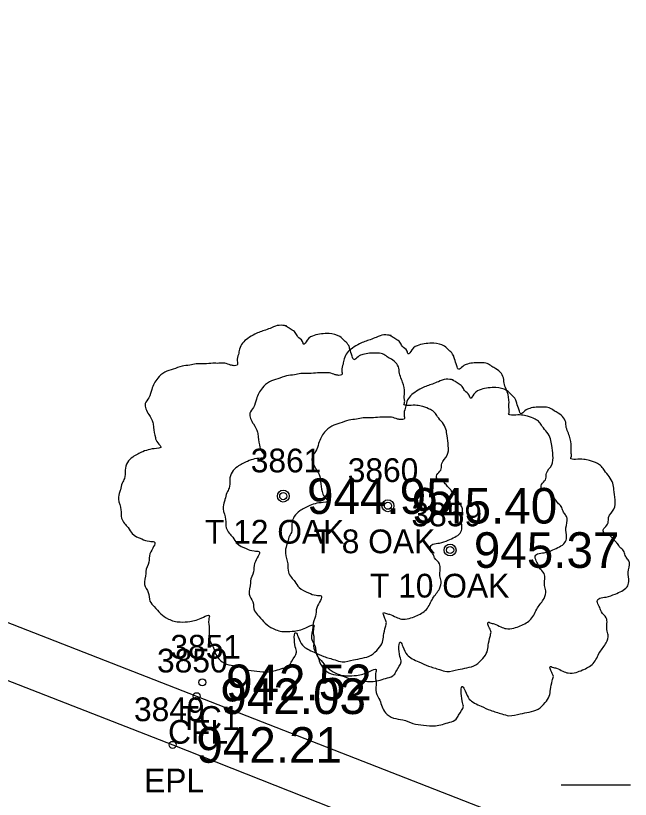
# Model space of a CAD drawing. Extents: x 1575382 to 1578175, y 1099175 to 1101955.
# Drawn here: x 1577597.19 to 1577623.09, y 1100831.49 to 1100864.5 of the extents above; entities that cross this region are included whole.
import ezdxf

# ---------------------------------------------------------------- set-up
doc = ezdxf.new("R2010")
doc.units = 0
for name, color, linetype in [('RD_EX_Conc', 7, 'Continuous'), ('RD_EX_Conc_txCode', 7, 'Continuous'), ('RD_EX_Road', 7, 'Continuous'), ('RD_EX_Road_txCode', 7, 'Continuous'), ('RD_EX_TX_Conc_ELEV', 7, 'Continuous'), ('RD_EX_TX_Road_ELEV', 7, 'Continuous'), ('RD_EX_TX_VEG_ELEV', 7, 'Continuous'), ('RD_EX_UT', 7, 'Continuous'), ('RD_EX_VEG', 7, 'Continuous'), ('RD_EX_VEG_txCode', 7, 'Continuous'), ('RD_HC_Data', 7, 'Continuous'), ('RD_SMD_Locator', 7, 'Continuous')]:
    doc.layers.add(name, color=color, linetype=linetype)

msp = doc.modelspace()

# ---------------------------------------------------------------- linework, layer by layer
at = {"layer": 'RD_EX_Conc'}
msp.add_lwpolyline([(1577521.961, 1100892.215), (1577519.026, 1100884.741), (1577517.864, 1100878.699), (1577519.281, 1100873.69), (1577525.338, 1100868.314), (1577559.486, 1100853.531), (1577604.815, 1100835.833), (1577651.288, 1100817.68)], dxfattribs=at)
at = {"layer": 'RD_EX_Road'}
msp.add_lwpolyline([(1577532.834, 1100925.692), (1577520.073, 1100893.352), (1577517.119, 1100885.443), (1577515.828, 1100878.695), (1577517.186, 1100872.6), (1577524.619, 1100866.376), (1577558.241, 1100851.545), (1577603.805, 1100833.782), (1577650.481, 1100815.34)], dxfattribs=at)
at = {"layer": 'RD_EX_UT'}
msp.add_line((1577620.17, 1100832.105), (1577623.1, 1100832.105), dxfattribs=at)
at = {"layer": 'RD_EX_VEG'}
for centre, radius in [((1577608.465, 1100844.262), 0.25), ((1577608.452, 1100844.243), 0.0001), ((1577612.874, 1100843.856), 0.25), ((1577612.861, 1100843.837), 0.0001), ((1577615.496, 1100841.99), 0.25), ((1577615.483, 1100841.971), 0.0001)]:
    msp.add_circle(centre, radius, dxfattribs=at)
for points in [[(1577608.597, 1100851.43), (1577608.297, 1100851.455), (1577607.972, 1100851.355), (1577607.722, 1100851.255), (1577607.497, 1100851.18), (1577607.272, 1100851.08), (1577606.972, 1100850.905), (1577606.748, 1100850.705), (1577606.623, 1100850.455), (1577606.573, 1100850.23), (1577606.523, 1100849.955), (1577606.523, 1100849.78), (1577606.398, 1100849.755), (1577606.248, 1100849.78), (1577605.998, 1100849.855), (1577605.748, 1100849.855), (1577605.498, 1100849.855), (1577605.148, 1100849.83), (1577604.798, 1100849.83), (1577604.524, 1100849.78), (1577604.199, 1100849.73), (1577603.824, 1100849.605), (1577603.474, 1100849.48), (1577603.174, 1100849.23), (1577602.924, 1100848.756), (1577602.799, 1100848.406), (1577602.649, 1100848.156), (1577602.799, 1100847.706), (1577602.974, 1100847.356), (1577602.999, 1100847.156), (1577603.074, 1100846.732), (1577603.174, 1100846.507), (1577603.299, 1100846.307), (1577603.224, 1100846.282), (1577602.849, 1100846.232), (1577602.549, 1100846.132), (1577602.125, 1100845.907), (1577601.9, 1100845.682), (1577601.8, 1100845.357), (1577601.775, 1100845.007), (1577601.675, 1100844.807), (1577601.6, 1100844.533), (1577601.575, 1100844.458), (1577601.525, 1100844.133), (1577601.625, 1100843.683), (1577601.65, 1100843.333), (1577601.775, 1100843.108), (1577601.925, 1100842.933), (1577602.1, 1100842.683), (1577602.499, 1100842.458), (1577602.824, 1100842.358), (1577603.024, 1100842.334), (1577602.849, 1100841.834), (1577602.799, 1100841.484), (1577602.674, 1100841.084), (1577602.674, 1100841.009), (1577602.624, 1100840.534), (1577602.774, 1100840.209), (1577602.849, 1100839.835), (1577603.024, 1100839.61), (1577603.299, 1100839.31), (1577603.624, 1100839.085), (1577604.124, 1100838.96), (1577604.524, 1100838.985), (1577605.098, 1100839.16), (1577605.348, 1100839.235), (1577605.323, 1100839.06), (1577605.348, 1100838.685), (1577605.348, 1100838.26), (1577605.498, 1100837.935), (1577605.598, 1100837.661), (1577605.748, 1100837.411), (1577606.073, 1100837.186), (1577606.473, 1100837.111), (1577606.897, 1100836.961), (1577607.347, 1100836.886), (1577607.847, 1100836.861), (1577608.447, 1100837.011), (1577608.722, 1100837.136), (1577608.822, 1100837.311), (1577609.022, 1100837.686), (1577608.972, 1100837.91), (1577608.997, 1100838.51), (1577609.096, 1100838.335), (1577609.271, 1100837.985), (1577609.771, 1100837.686), (1577610.171, 1100837.511), (1577610.646, 1100837.361), (1577610.946, 1100837.286), (1577611.42, 1100837.361), (1577611.795, 1100837.436), (1577612.17, 1100837.561), (1577612.47, 1100837.835), (1577612.645, 1100838.11), (1577612.695, 1100838.385), (1577612.77, 1100838.76), (1577612.82, 1100838.935)], [(1577612.82, 1100838.935), (1577612.745, 1100839.11), (1577612.695, 1100839.36), (1577612.77, 1100839.335), (1577612.945, 1100839.285), (1577613.22, 1100839.16), (1577613.445, 1100839.085), (1577613.769, 1100839.11), (1577614.044, 1100839.21), (1577614.494, 1100839.485), (1577614.769, 1100839.96), (1577615.044, 1100840.359), (1577615.119, 1100840.684), (1577615.069, 1100840.909), (1577615.044, 1100841.409), (1577614.844, 1100841.659), (1577614.794, 1100841.784), (1577614.694, 1100842.184), (1577614.769, 1100842.234), (1577615.044, 1100842.284), (1577615.419, 1100842.408), (1577615.694, 1100842.533), (1577615.919, 1100842.708), (1577615.993, 1100842.933), (1577615.969, 1100843.333), (1577616.018, 1100843.733), (1577615.944, 1100843.883), (1577615.844, 1100844.033), (1577615.769, 1100844.233), (1577615.619, 1100844.383), (1577615.519, 1100844.533), (1577615.419, 1100844.632), (1577615.294, 1100844.782), (1577615.119, 1100844.907), (1577614.969, 1100844.957), (1577614.919, 1100845.107), (1577615.069, 1100845.307), (1577615.119, 1100845.407), (1577615.144, 1100845.632), (1577615.369, 1100845.982), (1577615.419, 1100846.382), (1577615.369, 1100846.807), (1577615.319, 1100847.081), (1577615.169, 1100847.356), (1577614.969, 1100847.606), (1577614.844, 1100847.781), (1577614.669, 1100847.906), (1577614.344, 1100848.031), (1577614.094, 1100848.081), (1577613.744, 1100848.081), (1577613.545, 1100848.131), (1577613.57, 1100848.181), (1577613.57, 1100848.331), (1577613.57, 1100848.606), (1577613.495, 1100849.056), (1577613.345, 1100849.555), (1577613.345, 1100849.58), (1577613.245, 1100849.83), (1577613.02, 1100850.03), (1577612.845, 1100850.13), (1577612.645, 1100850.255), (1577612.395, 1100850.28), (1577612.095, 1100850.28), (1577611.82, 1100850.23), (1577611.62, 1100850.13), (1577611.445, 1100850.005), (1577611.37, 1100850.155), (1577611.271, 1100850.455), (1577611.221, 1100850.605), (1577611.071, 1100850.78), (1577610.846, 1100850.98), (1577610.396, 1100851.105), (1577609.771, 1100851.03), (1577609.471, 1100850.83), (1577609.321, 1100850.655), (1577609.271, 1100850.78), (1577609.071, 1100850.98), (1577608.972, 1100851.155), (1577608.797, 1100851.28), (1577608.647, 1100851.38), (1577608.547, 1100851.43)], [(1577613.006, 1100851.023), (1577612.706, 1100851.048), (1577612.381, 1100850.948), (1577612.131, 1100850.849), (1577611.906, 1100850.774), (1577611.681, 1100850.674), (1577611.381, 1100850.499), (1577611.157, 1100850.299), (1577611.032, 1100850.049), (1577610.982, 1100849.824), (1577610.932, 1100849.549), (1577610.932, 1100849.374), (1577610.807, 1100849.349), (1577610.657, 1100849.374), (1577610.407, 1100849.449), (1577610.157, 1100849.449), (1577609.907, 1100849.449), (1577609.557, 1100849.424), (1577609.207, 1100849.424), (1577608.933, 1100849.374), (1577608.608, 1100849.324), (1577608.233, 1100849.199), (1577607.883, 1100849.074), (1577607.583, 1100848.824), (1577607.333, 1100848.35), (1577607.208, 1100848), (1577607.058, 1100847.75), (1577607.208, 1100847.3), (1577607.383, 1100846.95), (1577607.408, 1100846.75), (1577607.483, 1100846.326), (1577607.583, 1100846.101), (1577607.708, 1100845.901), (1577607.633, 1100845.876), (1577607.258, 1100845.826), (1577606.958, 1100845.726), (1577606.534, 1100845.501), (1577606.309, 1100845.276), (1577606.209, 1100844.951), (1577606.184, 1100844.601), (1577606.084, 1100844.401), (1577606.009, 1100844.126), (1577605.984, 1100844.051), (1577605.934, 1100843.727), (1577606.034, 1100843.277), (1577606.059, 1100842.927), (1577606.184, 1100842.702), (1577606.334, 1100842.527), (1577606.509, 1100842.277), (1577606.908, 1100842.052), (1577607.233, 1100841.952), (1577607.433, 1100841.927), (1577607.258, 1100841.428), (1577607.208, 1100841.078), (1577607.083, 1100840.678), (1577607.083, 1100840.603), (1577607.033, 1100840.128), (1577607.183, 1100839.803), (1577607.258, 1100839.429), (1577607.433, 1100839.204), (1577607.708, 1100838.904), (1577608.033, 1100838.679), (1577608.533, 1100838.554), (1577608.933, 1100838.579), (1577609.507, 1100838.754), (1577609.757, 1100838.829), (1577609.732, 1100838.654), (1577609.757, 1100838.279), (1577609.757, 1100837.854), (1577609.907, 1100837.529), (1577610.007, 1100837.254), (1577610.157, 1100837.005), (1577610.482, 1100836.78), (1577610.882, 1100836.705), (1577611.306, 1100836.555), (1577611.756, 1100836.48), (1577612.256, 1100836.455), (1577612.856, 1100836.605), (1577613.131, 1100836.73), (1577613.231, 1100836.905), (1577613.431, 1100837.279), (1577613.381, 1100837.504), (1577613.406, 1100838.104), (1577613.505, 1100837.929), (1577613.68, 1100837.579), (1577614.18, 1100837.279), (1577614.58, 1100837.105), (1577615.055, 1100836.955), (1577615.355, 1100836.88), (1577615.829, 1100836.955), (1577616.204, 1100837.03), (1577616.579, 1100837.155), (1577616.879, 1100837.429), (1577617.054, 1100837.704), (1577617.104, 1100837.979), (1577617.179, 1100838.354), (1577617.229, 1100838.529)], [(1577617.229, 1100838.529), (1577617.154, 1100838.704), (1577617.104, 1100838.954), (1577617.179, 1100838.929), (1577617.354, 1100838.879), (1577617.629, 1100838.754), (1577617.854, 1100838.679), (1577618.178, 1100838.704), (1577618.453, 1100838.804), (1577618.903, 1100839.079), (1577619.178, 1100839.553), (1577619.453, 1100839.953), (1577619.528, 1100840.278), (1577619.478, 1100840.503), (1577619.453, 1100841.003), (1577619.253, 1100841.253), (1577619.203, 1100841.378), (1577619.103, 1100841.777), (1577619.178, 1100841.827), (1577619.453, 1100841.877), (1577619.828, 1100842.002), (1577620.103, 1100842.127), (1577620.328, 1100842.302), (1577620.402, 1100842.527), (1577620.378, 1100842.927), (1577620.427, 1100843.327), (1577620.353, 1100843.477), (1577620.253, 1100843.627), (1577620.178, 1100843.827), (1577620.028, 1100843.976), (1577619.928, 1100844.126), (1577619.828, 1100844.226), (1577619.703, 1100844.376), (1577619.528, 1100844.501), (1577619.378, 1100844.551), (1577619.328, 1100844.701), (1577619.478, 1100844.901), (1577619.528, 1100845.001), (1577619.553, 1100845.226), (1577619.778, 1100845.576), (1577619.828, 1100845.976), (1577619.778, 1100846.4), (1577619.728, 1100846.675), (1577619.578, 1100846.95), (1577619.378, 1100847.2), (1577619.253, 1100847.375), (1577619.078, 1100847.5), (1577618.753, 1100847.625), (1577618.503, 1100847.675), (1577618.153, 1100847.675), (1577617.954, 1100847.725), (1577617.979, 1100847.775), (1577617.979, 1100847.925), (1577617.979, 1100848.2), (1577617.904, 1100848.649), (1577617.754, 1100849.149), (1577617.754, 1100849.174), (1577617.654, 1100849.424), (1577617.429, 1100849.624), (1577617.254, 1100849.724), (1577617.054, 1100849.849), (1577616.804, 1100849.874), (1577616.504, 1100849.874), (1577616.229, 1100849.824), (1577616.029, 1100849.724), (1577615.854, 1100849.599), (1577615.779, 1100849.749), (1577615.68, 1100850.049), (1577615.63, 1100850.199), (1577615.48, 1100850.374), (1577615.255, 1100850.574), (1577614.805, 1100850.699), (1577614.18, 1100850.624), (1577613.88, 1100850.424), (1577613.73, 1100850.249), (1577613.68, 1100850.374), (1577613.48, 1100850.574), (1577613.381, 1100850.749), (1577613.206, 1100850.874), (1577613.056, 1100850.973), (1577612.956, 1100851.023)], [(1577615.628, 1100849.157), (1577615.328, 1100849.182), (1577615.003, 1100849.082), (1577614.753, 1100848.983), (1577614.528, 1100848.908), (1577614.303, 1100848.808), (1577614.004, 1100848.633), (1577613.779, 1100848.433), (1577613.654, 1100848.183), (1577613.604, 1100847.958), (1577613.554, 1100847.683), (1577613.554, 1100847.508), (1577613.429, 1100847.483), (1577613.279, 1100847.508), (1577613.029, 1100847.583), (1577612.779, 1100847.583), (1577612.529, 1100847.583), (1577612.179, 1100847.558), (1577611.829, 1100847.558), (1577611.555, 1100847.508), (1577611.23, 1100847.458), (1577610.855, 1100847.333), (1577610.505, 1100847.208), (1577610.205, 1100846.958), (1577609.955, 1100846.484), (1577609.83, 1100846.134), (1577609.68, 1100845.884), (1577609.83, 1100845.434), (1577610.005, 1100845.084), (1577610.03, 1100844.884), (1577610.105, 1100844.46), (1577610.205, 1100844.235), (1577610.33, 1100844.035), (1577610.255, 1100844.01), (1577609.88, 1100843.96), (1577609.58, 1100843.86), (1577609.156, 1100843.635), (1577608.931, 1100843.41), (1577608.831, 1100843.085), (1577608.806, 1100842.735), (1577608.706, 1100842.535), (1577608.631, 1100842.26), (1577608.606, 1100842.185), (1577608.556, 1100841.861), (1577608.656, 1100841.411), (1577608.681, 1100841.061), (1577608.806, 1100840.836), (1577608.956, 1100840.661), (1577609.131, 1100840.411), (1577609.53, 1100840.186), (1577609.855, 1100840.086), (1577610.055, 1100840.061), (1577609.88, 1100839.562), (1577609.83, 1100839.212), (1577609.705, 1100838.812), (1577609.705, 1100838.737), (1577609.655, 1100838.262), (1577609.805, 1100837.937), (1577609.88, 1100837.563), (1577610.055, 1100837.338), (1577610.33, 1100837.038), (1577610.655, 1100836.813), (1577611.155, 1100836.688), (1577611.555, 1100836.713), (1577612.129, 1100836.888), (1577612.379, 1100836.963), (1577612.354, 1100836.788), (1577612.379, 1100836.413), (1577612.379, 1100835.988), (1577612.529, 1100835.663), (1577612.629, 1100835.388), (1577612.779, 1100835.139), (1577613.104, 1100834.914), (1577613.504, 1100834.839), (1577613.929, 1100834.689), (1577614.378, 1100834.614), (1577614.878, 1100834.589), (1577615.478, 1100834.739), (1577615.753, 1100834.864), (1577615.853, 1100835.039), (1577616.053, 1100835.413), (1577616.003, 1100835.638), (1577616.028, 1100836.238), (1577616.128, 1100836.063), (1577616.303, 1100835.713), (1577616.802, 1100835.413), (1577617.202, 1100835.239), (1577617.677, 1100835.089), (1577617.977, 1100835.014), (1577618.452, 1100835.089), (1577618.826, 1100835.164), (1577619.201, 1100835.289), (1577619.501, 1100835.563), (1577619.676, 1100835.838), (1577619.726, 1100836.113), (1577619.801, 1100836.488), (1577619.851, 1100836.663)], [(1577619.851, 1100836.663), (1577619.776, 1100836.838), (1577619.726, 1100837.088), (1577619.801, 1100837.063), (1577619.976, 1100837.013), (1577620.251, 1100836.888), (1577620.476, 1100836.813), (1577620.801, 1100836.838), (1577621.075, 1100836.938), (1577621.525, 1100837.213), (1577621.8, 1100837.687), (1577622.075, 1100838.087), (1577622.15, 1100838.412), (1577622.1, 1100838.637), (1577622.075, 1100839.137), (1577621.875, 1100839.387), (1577621.825, 1100839.512), (1577621.725, 1100839.911), (1577621.8, 1100839.961), (1577622.075, 1100840.011), (1577622.45, 1100840.136), (1577622.725, 1100840.261), (1577622.95, 1100840.436), (1577623.025, 1100840.661), (1577623, 1100841.061), (1577623.05, 1100841.461), (1577622.975, 1100841.611), (1577622.875, 1100841.761), (1577622.8, 1100841.961), (1577622.65, 1100842.11), (1577622.55, 1100842.26), (1577622.45, 1100842.36), (1577622.325, 1100842.51), (1577622.15, 1100842.635), (1577622, 1100842.685), (1577621.95, 1100842.835), (1577622.1, 1100843.035), (1577622.15, 1100843.135), (1577622.175, 1100843.36), (1577622.4, 1100843.71), (1577622.45, 1100844.11), (1577622.4, 1100844.534), (1577622.35, 1100844.809), (1577622.2, 1100845.084), (1577622, 1100845.334), (1577621.875, 1100845.509), (1577621.7, 1100845.634), (1577621.375, 1100845.759), (1577621.125, 1100845.809), (1577620.776, 1100845.809), (1577620.576, 1100845.859), (1577620.601, 1100845.909), (1577620.601, 1100846.059), (1577620.601, 1100846.334), (1577620.526, 1100846.783), (1577620.376, 1100847.283), (1577620.376, 1100847.308), (1577620.276, 1100847.558), (1577620.051, 1100847.758), (1577619.876, 1100847.858), (1577619.676, 1100847.983), (1577619.426, 1100848.008), (1577619.126, 1100848.008), (1577618.851, 1100847.958), (1577618.651, 1100847.858), (1577618.477, 1100847.733), (1577618.402, 1100847.883), (1577618.302, 1100848.183), (1577618.252, 1100848.333), (1577618.102, 1100848.508), (1577617.877, 1100848.708), (1577617.427, 1100848.833), (1577616.802, 1100848.758), (1577616.502, 1100848.558), (1577616.352, 1100848.383), (1577616.303, 1100848.508), (1577616.103, 1100848.708), (1577616.003, 1100848.883), (1577615.828, 1100849.008), (1577615.678, 1100849.107), (1577615.578, 1100849.157)]]:
    msp.add_spline(points, degree=3, dxfattribs=at)
at = {"layer": 'RD_SMD_Locator'}
for centre in [(1577608.465, 1100844.262), (1577612.874, 1100843.856), (1577615.496, 1100841.99), (1577605.055, 1100836.417), (1577604.815, 1100835.833), (1577603.805, 1100833.782)]:
    msp.add_circle(centre, 0.15, dxfattribs=at)

# ---------------------------------------------------------------- texts
at = {"layer": 'RD_EX_Conc_txCode'}
for s, p in [('3851', (1577603.709, 1100837.417)), ('3850', (1577603.145, 1100836.833)), ('TC1', (1577604.095, 1100834.417)), ('CFL', (1577603.61, 1100833.833))]:
    msp.add_text(s, height=1, dxfattribs=at).set_placement(p)
at = {"layer": 'RD_EX_Road_txCode'}
for s, p in [('3849', (1577602.175, 1100834.782)), ('EPL', (1577602.6, 1100831.782))]:
    msp.add_text(s, height=1, dxfattribs=at).set_placement(p)
at = {"layer": 'RD_EX_TX_Conc_ELEV'}
for s, p in [('942.52', (1577606.055, 1100835.667)), ('942.03', (1577605.815, 1100835.083))]:
    msp.add_text(s, height=1.5, dxfattribs=at).set_placement(p)
at = {"layer": 'RD_EX_TX_Road_ELEV'}
msp.add_text('942.21', height=1.5, dxfattribs=at).set_placement((1577604.805, 1100833.032))
at = {"layer": 'RD_EX_TX_VEG_ELEV'}
for s, p in [('944.95', (1577609.465, 1100843.512)), ('945.40', (1577613.874, 1100843.106)), ('945.37', (1577616.496, 1100841.24))]:
    msp.add_text(s, height=1.5, dxfattribs=at).set_placement(p)
at = {"layer": 'RD_EX_VEG_txCode'}
for s, p in [('3861', (1577607.095, 1100845.262)), ('3860', (1577611.181, 1100844.856)), ('3859', (1577613.866, 1100842.99)), ('T 12 OAK', (1577605.166, 1100842.262)), ('T 8 OAK', (1577609.74, 1100841.856)), ('T 10 OAK', (1577612.118, 1100839.99))]:
    msp.add_text(s, height=1, dxfattribs=at).set_placement(p)
at = {"layer": 'RD_HC_Data'}
msp.add_text('S 68%%d 42\' 25" E', height=6, rotation=338.707, dxfattribs=at).set_placement((1577575.398, 1100834.085))

doc.saveas('drawing.dxf')
